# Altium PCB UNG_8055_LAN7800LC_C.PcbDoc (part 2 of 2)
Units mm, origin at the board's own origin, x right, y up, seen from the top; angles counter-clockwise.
Board outline 54.74 x 22.1 mm, 4 copper layers (Top Layer 1, Inner Layer 2, Internal Plane 3, Bottom Layer 4), stack 1.529 mm thick; 68 components, 53 nets, 222 pads, 271 vias.
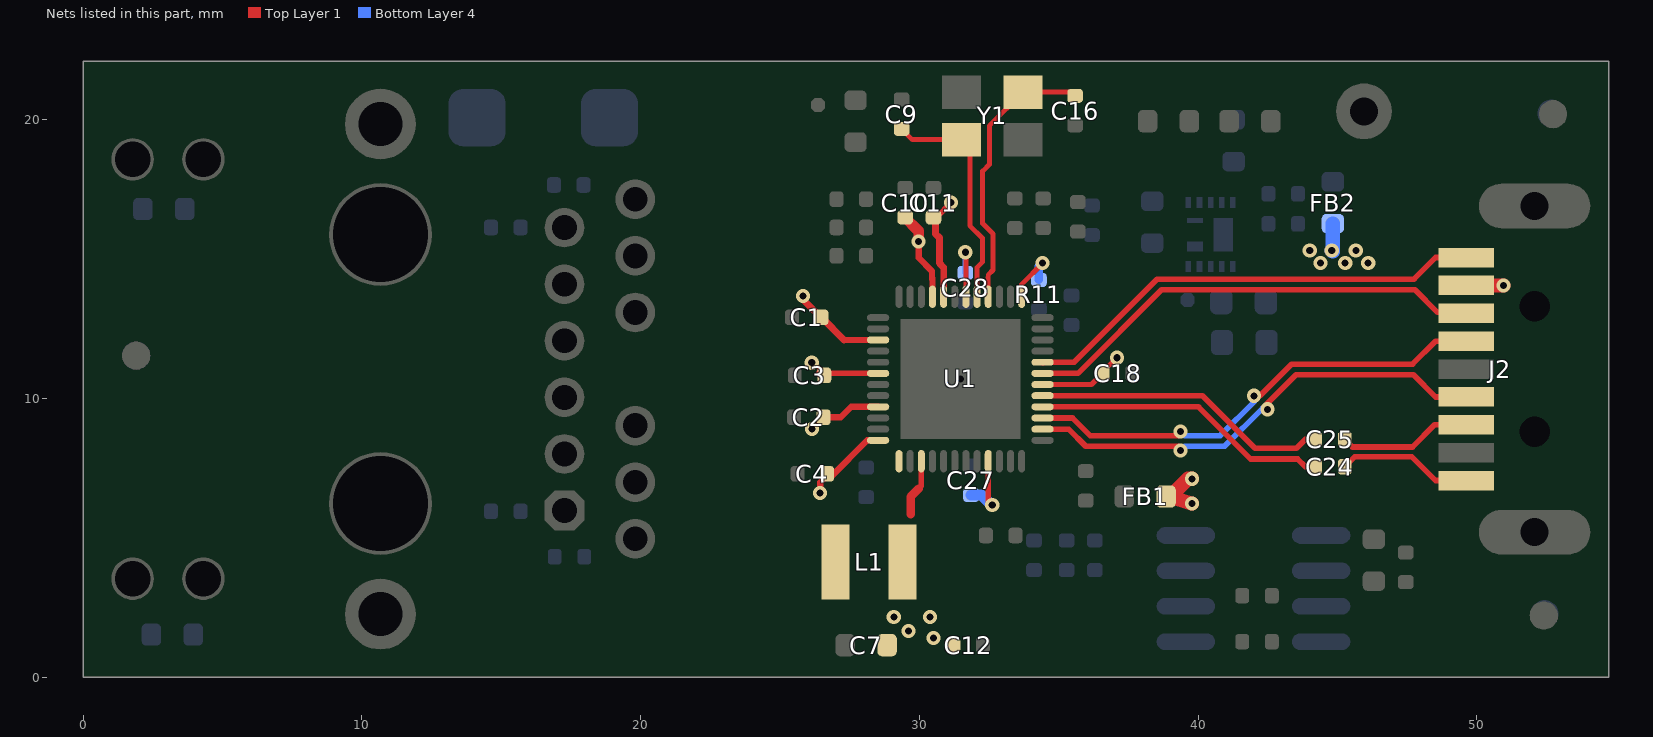
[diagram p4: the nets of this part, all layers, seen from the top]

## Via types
v1: diameter 0.508, hole 0.254, Top Layer 1 to Bottom Layer 4, tented both sides, 245 vias
v2: diameter 0.508, hole 0.254, Top Layer 1 to Bottom Layer 4, 26 vias

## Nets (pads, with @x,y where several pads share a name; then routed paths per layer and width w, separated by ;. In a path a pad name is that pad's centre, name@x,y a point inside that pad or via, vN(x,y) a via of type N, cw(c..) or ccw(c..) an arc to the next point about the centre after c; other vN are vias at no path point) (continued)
USB2D_N: J2.2 U1.27 | length 17.2
  Top Layer 1 w0.203: U1.27@34.421,9.293 35.492,9.293 36.124,8.661 39.294,8.661 39.37,8.738 v1(39.37,8.814) ; v1(42.005,10.09) 42.221,10.09 43.358,11.227 47.696,11.227 48.518,12.049 J2.2@49.62,12.049
  Bottom Layer 4 w0.203: v1(39.37,8.814) 39.522,8.661 40.792,8.661 42.037,9.906 42.037,10.058 v1(42.005,10.09)
USB2D_P: J2.3 U1.26 | length 17.2
  Top Layer 1 w0.203: U1.26@34.421,8.893 35.353,8.893 35.966,8.28 39.294,8.28 39.37,8.204 v1(39.37,8.128) ; v1(42.49,9.605) 42.49,9.821 43.516,10.846 47.722,10.846 48.518,10.049 J2.3@49.62,10.049
  Bottom Layer 4 w0.203: v1(39.37,8.128) 39.522,8.28 40.95,8.28 42.306,9.637 42.459,9.637 v1(42.49,9.605)
USB3RX_N: J2.8 U1.31 | length 17
  Top Layer 1 w0.203: U1.31@34.25,10.9 34.259,10.891 U1.31@34.421,10.891 ; U1.31@34.421,10.893 35.689,10.893 38.69,13.894 47.777,13.894 48.59,13.081 49.588,13.081 J2.8@49.62,13.049
USB3RX_P: J2.9 U1.32 | length 16.8
  Top Layer 1 w0.203: U1.32@34.417,11.272 34.421,11.272 34.434,11.272 34.438,11.276 U1.32@34.439,11.278 ; U1.32@34.421,11.293 35.55,11.293 38.532,14.275 47.744,14.275 48.518,15.049 J2.9@49.62,15.049
USB3TX1_N: C24.1 J2.5 | length 4.9
  Top Layer 1 w0.203: C24.1@45.259,7.544 45.615,7.899 47.668,7.899 48.518,7.049 J2.5@49.62,7.049
USB3TX1_P: C25.1 J2.6 | length 4.8
  Top Layer 1 w0.203: C25.1@45.259,8.531 45.536,8.255 47.688,8.255 48.482,9.049 J2.6@49.62,9.049
USB3TX_N: C24.2 U1.28 | length 10.7
  Top Layer 1 w0.203: U1.28@34.421,9.693 40.014,9.693 41.885,7.823 43.568,7.823 43.848,7.544 C24.2@44.199,7.544
USB3TX_P: C25.2 U1.29 | length 10.7
  Top Layer 1 w0.203: U1.29@34.421,10.093 40.153,10.093 42.04,8.207 43.523,8.207 43.848,8.531 C25.2@44.199,8.531
USBRBIAS: R11.2 U1.37 | length 2
  Top Layer 1 w0.178: U1.37@33.671,13.643 33.671,14.087 34.417,14.833 v1(34.417,14.859)
  Bottom Layer 4 w0.305: R11.2@34.29,14.246 v1@34.29,14.732
VBUS: FB2.1 J2.1 | length 2.4
  Top Layer 1 w0.254: v1(50.95,14.049) v1@50.955,14.049
  Top Layer 1 w0.508: J2.1@49.62,14.049 v1(50.95,14.049)
  Bottom Layer 4 w0.508: v1(44.793,15.303) 44.831,15.265 FB2.1@44.831,16.268
  other v1: 44.386,14.859 45.275,14.859 46.101,14.859 44.005,15.303 45.656,15.303
VDD12: C7.2 C11.2 C12.2 C18.2 C27.2 C28.2 FB1.2 L1.2 U1.15 U1.21 U1.30 U1.42 U1.44 | length 15.5
  Top Layer 1 w0.178: U1.42@31.671,13.643 v1@31.671,15.218 ; U1.30@34.421,10.493 36.173,10.493 C18.2@36.576,10.897 ; C18.2@36.579,10.897 36.579,10.951 v1@37.059,11.43
  Top Layer 1 w0.203: 29.972,6.756 30.071,6.855 U1.15@30.071,7.743 ; C11.2@30.505,16.488 30.61,16.488 v1(31.14,17.018) ; U1.21@32.471,7.743 32.471,6.239 v1@32.588,6.121
  Top Layer 1 w0.229: U1.44@30.871,13.643 30.871,14.697
  Top Layer 1 w0.254: C11.2@30.505,16.383 30.582,16.307 30.582,15.898 30.721,15.759 30.721,14.847 30.871,14.697 ; v1(31.648,15.24) v1@31.671,15.218
  Top Layer 1 w0.305: 29.693,5.842 29.693,6.477 29.972,6.756
  Top Layer 1 w0.508: v1(39.776,6.223) 39,6.477 39.635,7.112 v1(39.776,7.112)
  Bottom Layer 4 w0.203: C28.2@31.648,14.5 v1@31.648,15.113
  Bottom Layer 4 w0.381: C27.2@31.852,6.531 32.229,6.531 v1@32.588,6.172
  other v1: 30.505,1.397 29.616,1.651 29.083,2.159 30.378,2.159 32.614,6.172 37.084,11.455
VDD12_SW_OUT: L1.1 U1.13
VDD25: C1.2 C2.2 C3.2 C4.2 C10.2 U1.3 U1.6 U1.9 U1.12 U1.45 | length 16.1
  Top Layer 1 w0.152: v1@25.991,8.903 v1(26.153,8.903) ; v1@26.067,11.125 v1@26.141,11.199 ; v1(26.141,11.277) v1@26.141,11.199 ; C3.2@26.437,10.943 26.459,10.922 26.48,10.943 26.51,10.973 26.212,11.27 v1@26.141,11.199
  Top Layer 1 w0.178: v1(26.153,8.903) 26.06,8.81 26.037,8.786 ccw(c26.037,8.899) 26.116,8.819 C2.2@26.594,9.296
  Top Layer 1 w0.203: C3.2@26.667,10.893 U1.6@28.521,10.893 ; 27.302,12.093 U1.3@28.521,12.093
  Top Layer 1 w0.229: v1(26.441,6.604) 26.441,6.985 26.692,7.236 C4.2@26.692,7.29 ; C3.2@26.518,10.744 C3.2@26.667,10.893 ; C2.2@26.565,9.322 27.179,9.322 27.551,9.693 U1.9@28.521,9.693 ; C4.2@26.692,7.188 26.829,7.188 28.135,8.493 U1.12@28.521,8.493 ; v1(29.972,15.621) 29.972,15.039 30.455,14.556 30.455,14.275 ; U1.45@30.471,13.643 30.471,14.31
  Top Layer 1 w0.254: v1(25.832,13.665) 25.832,13.538 C1.2@26.454,12.916 ; C3.2@26.437,10.943 26.48,10.943 C3.2@26.67,10.943 ; C1.2@26.518,12.878 27.302,12.093
  Top Layer 1 w0.381: C10.2@29.464,16.51 29.972,16.002 v1(29.972,15.621)
XI: C16.2 U1.40 Y1.3 | length 10.1
  Top Layer 1 w0.178: 32.461,14.326 32.471,14.335 ; U1.40@32.471,13.643 32.471,14.335 ; C16.2@35.585,20.828 35.433,20.98 Y1.3@33.718,20.98 32.512,19.774 32.512,18.39 32.271,18.148 32.271,16.269 32.639,15.9 32.639,14.6 32.471,14.431 32.471,14.335
XO: C9.2 U1.41 Y1.1 | length 8.3
  Top Layer 1 w0.178: C9.2@29.362,19.663 29.747,19.279 Y1.1@31.509,19.279 ; Y1.1@31.557,19.238 31.813,18.981 31.813,16.192 32.258,15.748 32.258,14.884 32.071,14.697 U1.41@32.071,13.643
pads on no net: FID1.1 FID2.1 FID3.1 FID4.1 FID5.1 FID6.1 J2.MH U3.7

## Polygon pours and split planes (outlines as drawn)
GND on Top Layer 1 "Top Layer-No Net" (solid, pour order 68): 52.299,13.284 50.444,13.284 50.267,13.462 50.241,13.487 49.454,13.487 46.457,13.487 46.406,13.487 46.152,13.741 46.126,13.767 46.126,13.919 46.126,14.3 46.279,14.453 46.304,14.478 46.457,14.478 50.927,14.478 51.46,13.945 51.689,13.716 52.299,13.716
NetC17_2 on Top Layer 1 "Top Layer-No Net" (solid, pour order 50): 37.49,6.096 37.49,6.858 37.49,7.112 37.363,7.239 36.982,7.239 36.601,7.239 36.093,7.747 35.331,8.509 34.95,8.509 34.315,8.509 34.188,8.382 34.188,8.255 34.569,7.874 34.696,7.874 34.823,7.874 35.458,7.239 35.585,7.112 36.093,7.112 36.22,7.112 36.474,6.858 36.474,6.477 36.474,6.096 36.601,5.969 37.109,5.969 37.363,5.969 37.49,6.096
VDD12 on Top Layer 1 "Top Layer-No Net" (solid, pour order 8): 28.892,2.603 28.702,2.413 28.702,1.27 28.702,0.889 28.829,0.762 29.21,0.762 31.369,0.762 31.369,1.016 31.369,1.651 31.242,1.778 30.226,2.794 30.226,3.683 30.226,5.969 29.972,6.223 29.845,6.35 29.591,6.35 29.337,6.096 28.892,5.651
VDD12_SW_OUT on Top Layer 1 "Top Layer-No Net" (solid, pour order 18): 26.314,2.718 27.419,2.718 27.876,3.175 27.876,6.032 28.219,6.375 28.854,7.01 29.362,7.518 29.362,8.128 28.981,8.128 28.473,7.62 28.016,7.62 27.457,7.061 25.844,5.448 25.844,3.188
3V3_BOARD on Top Layer 1 "Top Layer-No Net" (solid, pour order 28): 33.426,13.462 33.426,14.224 33.426,14.351 34.442,15.367 34.696,15.621 34.696,15.875 34.696,16.256 34.315,16.256 33.172,16.256 33.045,16.129 33.045,16.002 33.045,14.605 32.791,14.351 32.791,13.335 33.426,13.335
3V3_BOARD on Top Layer 1 "Top Layer-No Net" (solid, pour order 32): 34.112,12.776 34.519,12.776 34.9,12.776 35.712,13.589 35.712,14.224 35.712,14.478 35.585,14.605 35.458,14.732 35.331,14.732 35.204,14.732 34.823,14.351 34.823,13.589 34.823,13.335 34.569,13.081 34.188,13.081 34.061,12.954 34.061,12.827
GND on Top Layer 1 "Top Layer-No Net" (solid, pour order 64): 37.668,14.224 38.303,14.224 38.43,14.351 38.43,14.478 38.43,14.732 38.43,15.748 38.811,16.129 38.938,16.256 39.827,16.256 40.589,16.256 40.716,16.383 40.716,16.764 40.716,19.05 40.589,19.177 40.081,19.177 39.192,19.177 39.065,19.304 39.065,19.431 39.065,20.066 39.065,20.32 38.938,20.447 37.795,20.447 37.668,20.447 37.541,20.32 37.541,19.685 37.541,19.304 37.668,19.177 37.922,19.177 38.557,19.177 38.938,18.796 39.065,18.669 39.065,18.161 39.065,17.78 39.192,17.653 39.446,17.653 40.208,17.653 40.335,17.526 40.335,17.399 40.335,16.637 40.208,16.51 39.954,16.51 39.573,16.51 39.065,16.51 37.287,16.51 37.16,16.383 37.16,16.129 37.16,14.351 37.287,14.224
GND on Top Layer 1 "Top Layer-No Net" (solid, pour order 66): 14.034,0.635 54.229,0.635 54.229,21.59 43.18,21.59 14.034,21.59
RJ45_CHASSIS on Top Layer 1 "Top Layer-No Net" (solid, pour order 76): 0.508,0.635 13.843,0.635 13.843,21.59 0.508,21.59
VBUS on Bottom Layer 4 "Top Layer-No Net" (solid, pour order 52): 43.434,15.596 43.713,15.875 44.094,16.256 46.126,16.256 46.507,15.875 46.507,15.113 46.507,14.732 46.38,14.605 46.253,14.478 44.602,14.478 43.434,14.478
5V_BOARD on Bottom Layer 4 "Top Layer-No Net" (solid, pour order 60): 40.894,17.59 41.148,17.335 42.189,17.335 45.352,17.335 45.415,17.399 45.491,17.475 45.491,17.932 45.491,18.593 45.415,18.669 45.314,18.771 44.298,18.771 41.059,18.771 40.894,18.605
3V3_BOARD on Bottom Layer 4 "Top Layer-No Net" (solid, pour order 56): 37.389,16.764 38.659,16.764 38.938,16.764 39.065,16.764 39.446,16.764 39.446,17.399 38.938,17.399 38.811,17.526 38.811,17.78 38.811,18.542 38.811,18.669 38.684,18.796 37.414,18.796 37.16,18.796 37.033,18.669 37.033,18.288 37.033,16.891 37.16,16.764
VDD25 on Bottom Layer 4 "Top Layer-No Net" (solid, pour order 22): 26.949,6.477 26.949,13.589 27.711,14.351 30.251,14.351 30.366,14.465 30.366,15.113 30.378,15.24 30.378,15.494 30.378,15.748 30.251,15.875 29.997,15.875 29.108,15.875 27.33,15.875 26.314,15.875 26.187,15.875 26.06,15.875 25.806,15.875 26.441,15.621 25.425,15.621 25.425,14.351 25.425,13.97 25.425,13.462 25.425,6.35 25.679,6.096 26.314,6.096 26.695,6.096 26.822,6.223 26.949,6.35
GND on Bottom Layer 4 "Top Layer-No Net" (solid, pour order 26): 27.711,7.112 34.696,7.112 35.966,7.112 36.347,7.493 36.347,10.033 36.347,12.446 36.22,12.573 35.966,12.827 35.458,12.827 34.95,12.827 34.823,12.827 34.696,12.954 34.696,13.335 34.696,13.589 32.41,13.589 27.584,13.589 27.33,13.335 27.33,12.573 27.33,7.366 27.584,7.112
GND on Bottom Layer 4 "Top Layer-No Net" (solid, pour order 70): 14.034,0.635 54.229,0.635 54.229,21.59 43.18,21.59 14.034,21.59
RJ45_CHASSIS on Bottom Layer 4 "Top Layer-No Net" (solid, pour order 78): 0.508,0.635 13.843,0.635 13.843,21.59 0.508,21.59
GND on Inner Layer 2 (split plane): 54.354,0.383 14.327,0.383 14.327,21.715 54.354,21.715
RJ45_CHASSIS on Inner Layer 2 (split plane): 13.562,0.383 0.383,0.383 0.383,21.715 13.562,21.715
VBUS on Internal Plane 3 (split plane): 51.242,14.678 51.242,13.833 50.873,13.464 44.123,13.464 43.78,13.808 43.5,14.087 43.5,15.44 44.186,16.127 49.794,16.127
3V3_BOARD on Internal Plane 3 (split plane): 46.924,20.711 46.924,20.002 46.924,19.739 46.2,19.015 45.793,18.608 45.085,18.608 45.035,18.598 44.993,18.57 41.945,15.522 41.917,15.48 41.908,15.43 41.908,14.722 41.793,14.607 36.703,14.607 36.653,14.598 36.611,14.57 36.078,14.036 36.05,13.994 36.04,13.945 36.04,13.591 35.296,13.591 32.21,16.678 32.21,17.907 32.2,17.957 32.172,17.999 31.664,18.507 31.622,18.535 31.572,18.544 30.937,18.544 30.888,18.535 30.846,18.507 30.452,18.113 30.424,18.071 30.414,18.021 30.414,15.824 30.424,15.775 30.452,15.733 31.671,14.513 31.713,14.485 31.763,14.476 32.014,14.476 32.039,14.45 34.11,12.38 34.11,8.309 33.17,7.368 32.893,7.368 32.843,7.359 32.801,7.331 32.547,7.077 31.862,6.391 31.834,6.349 31.824,6.299 31.824,5.207 31.834,5.157 31.862,5.115 32.116,4.861 32.158,4.833 32.207,4.824 35.1,4.824 35.888,4.036 35.888,2.975 35.329,2.415 31.598,2.415 31.585,2.413 31.572,2.415 31.245,2.415 30.902,2.759 30.86,2.787 30.81,2.796 28.514,2.796 28.514,2.857 28.514,6.614 28.756,6.856 30.289,6.856 30.339,6.865 30.381,6.893 31.905,8.417 31.933,8.459 31.943,8.509 31.943,12.255 31.933,12.305 31.905,12.347 29.022,15.23 29.022,17.335 29.012,17.385 28.984,17.427 28.413,17.999 28.371,18.027 28.321,18.036 16.818,18.036 16.512,18.342 16.512,19.06 16.792,19.339 16.881,19.429 42.418,19.429 42.468,19.438 42.51,19.466 44.123,21.08 46.555,21.08
VDD12 on Internal Plane 3 (split plane): 31.951,17.853 31.951,16.624 31.961,16.575 31.989,16.533 32.674,15.847 33.055,15.466 35.151,13.37 35.193,13.342 35.242,13.333 36.116,13.333 37.539,11.91 37.539,11.204 36.789,10.455 36.761,10.413 36.751,10.363 36.751,10.033 36.751,8.509 36.761,8.459 36.789,8.417 37.234,7.973 37.276,7.945 37.325,7.935 38.808,7.935 39.278,7.465 39.32,7.437 39.37,7.427 39.837,7.427 40.206,7.058 40.206,6.921 40.206,5.105 40.206,4.191 40.206,2.642 40.206,0.383 28.514,0.383 28.514,1.918 28.514,2.538 30.757,2.538 31.1,2.194 31.142,2.166 31.191,2.157 31.572,2.157 31.585,2.159 31.598,2.157 35.382,2.157 35.432,2.166 35.474,2.194 36.109,2.829 36.137,2.871 36.147,2.921 36.147,4.089 36.137,4.139 36.109,4.181 35.245,5.045 35.203,5.073 35.154,5.082 32.261,5.082 32.083,5.261 32.083,6.246 32.731,6.893 32.947,7.11 33.223,7.11 33.273,7.119 33.315,7.147 34.331,8.163 34.359,8.205 34.369,8.255 34.369,12.433 34.359,12.483 34.331,12.525 32.223,14.633 32.159,14.697 32.117,14.725 32.067,14.734 31.816,14.734 30.673,15.878 30.673,17.968 30.991,18.286 31.519,18.286
RJ45_CHASSIS on Internal Plane 3 (split plane): 13.587,0.383 0.383,0.383 0.383,21.715 13.587,21.715
GND on Internal Plane 3 (split plane): 54.354,0.383 40.465,0.383 40.465,2.642 40.465,5.105 40.465,7.112 40.455,7.162 40.427,7.204 39.982,7.648 39.94,7.676 39.891,7.686 39.424,7.686 38.954,8.156 38.912,8.184 38.862,8.194 37.379,8.194 37.01,8.563 37.01,10.31 37.76,11.059 37.788,11.101 37.798,11.151 37.798,11.963 37.788,12.013 37.76,12.055 36.299,13.516 36.299,13.891 36.757,14.349 41.846,14.349 41.896,14.358 41.938,14.386 42.129,14.577 42.157,14.619 42.166,14.668 42.166,15.377 45.139,18.349 45.847,18.349 45.897,18.359 45.939,18.387 46.383,18.831 47.145,19.593 47.173,19.635 47.183,19.685 47.183,20.764 47.173,20.814 47.145,20.856 46.701,21.301 46.659,21.329 46.609,21.338 44.069,21.338 44.019,21.329 43.977,21.301 42.364,19.687 16.827,19.687 16.778,19.678 16.736,19.65 16.609,19.523 16.291,19.205 16.263,19.163 16.254,19.113 16.254,18.288 16.263,18.238 16.291,18.196 16.672,17.815 16.714,17.787 16.764,17.778 28.267,17.778 28.763,17.282 28.763,15.176 28.773,15.127 28.801,15.085 31.684,12.202 31.684,8.563 30.236,7.114 28.702,7.114 28.652,7.105 28.61,7.077 28.293,6.759 28.265,6.717 28.255,6.667 28.255,2.857 28.255,2.667 28.255,1.918 28.255,0.383 14.353,0.383 14.353,21.715 54.354,21.715

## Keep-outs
Keep-Out Layer:
  text ".Layer_Name" at 239.425,-136.66 h0.51

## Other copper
Top Layer 1:
  pour cut-out: 29.019,13.208 33.972,13.208 33.972,8.191 29.019,8.191
  text ".Layer_Name" at -4.293,-12.065 h1.52
  text ".Layer_Name" at 250.114,-136.296 h2.54
  text ".ProjectRevisionART" at 272.499,-136.503 h2.54
Bottom Layer 4:
  region net NetTP2_1: 39.56,15.113 39.624,15.176 39.624,15.621 40.132,15.621 40.132,14.541 39.56,14.541
  region net 3V3_BOARD: 39.56,17.081 40.132,17.081 40.132,16.701 40.195,16.637 40.195,16.256 39.56,16.256
  pour cut-out: 12.217,18.517 12.344,18.39 15.545,18.39 15.926,18.771 15.926,21.311 15.697,21.539 12.421,21.539 12.217,21.336
  text "PCB-UNG8055-C0" at 6.794,14.922 h1.4 r90
  text ".Layer_Name" at -4.166,-11.938 h1.52
  text ".Layer_Name" at 250.063,-136.398 h2.54
  text ".ProjectRevisionART" at 272.517,-136.5 h2.54
Inner Layer 2 (plane layer: these items are gaps in the copper):
  lines w0.762: 13.945,0 13.945,22.034
  text ".Layer_Name" at -3.607,-11.836 h2.79
  text ".Layer_Name" at 249.936,-136.398 h2.79
  text ".ProjectRevisionART" at 272.499,-136.503 h2.54
Internal Plane 3 (plane layer: these items are gaps in the copper):
  lines w0.254: 28.397,0.127 28.384,0.14 28.384,1.918 28.384,2.857 28.384,2.667 ; 31.572,2.286 31.191,2.286 30.81,2.667 28.384,2.667 ; 31.598,2.286 35.382,2.286 36.017,2.921 36.017,4.089 35.154,4.953 34.011,4.953 ; 32.766,15.938 33.147,15.557 ; 33.083,7.239 32.893,7.239 ; 34.239,4.953 32.207,4.953 31.953,5.207 31.953,6.299 32.639,6.985 32.893,7.239 ; 36.881,10.033 36.881,10.363 ; 40.335,0 40.335,2.642 40.335,5.105 ; 40.335,4.191 40.335,7.112 ; 40.335,6.921 40.335,7.112 ; 46.291,18.923 45.847,18.479 ; 47.053,20.002 47.053,19.685 ; 28.384,2.667 28.384,6.667 28.702,6.985 29.591,6.985 30.289,6.985 31.813,8.509 31.813,12.255 28.892,15.176 28.892,17.335 28.321,17.907 28.003,17.907 16.764,17.907 16.383,18.288 16.383,19.113 16.7,19.431 16.827,19.558 42.418,19.558 44.069,21.209 46.609,21.209 47.053,20.764 47.053,19.685 ; 32.893,7.239 33.223,7.239 34.239,8.255 34.239,12.433 32.131,14.541 32.067,14.605 31.763,14.605 30.543,15.824 30.543,18.021 30.937,18.415 31.572,18.415 32.08,17.907 32.08,16.624 35.242,13.462 35.814,13.462 ; 35.814,13.462 36.17,13.462 ; 35.814,13.462 36.17,13.462 ; 36.17,13.462 36.17,13.945 36.703,14.478 41.846,14.478 42.037,14.668 42.037,15.43 45.085,18.479 45.847,18.479 ; 36.17,13.462 37.668,11.963 37.668,11.151 36.881,10.363 ; 36.881,10.363 36.881,8.509 37.325,8.064 38.862,8.064 39.37,7.556 39.891,7.556 40.335,7.112 ; 45.847,18.479 47.053,19.685 ; 43.37,14.034 43.37,15.494 44.132,16.256 49.847,16.256 51.371,14.732 51.371,13.779 50.927,13.335 44.069,13.335 43.688,13.716 43.37,14.034
  lines w0.762: 13.97,0 13.97,22.098
  text ".Layer_Name" at -3.962,-12.217 h2.79
  text ".ProjectRevisionART" at 272.517,-136.5 h2.54
  text ".Layer_Name" at 250.317,-136.652 h2.79

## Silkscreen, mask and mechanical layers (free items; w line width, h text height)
Top Overlay:
  lines w0.254: 0.508,20.149 4.318,20.149 8.588,20.149
  text "PME" at 23.622,19.748 h1.37
  text "\"3V3\"" at 40.576,17.97 h1.52
  text "3V3" at 45.021,17.843 h1.52
  text "*h" at 35.115,12.383 h2.79
  text "LAN7800" at 35.306,8.826 h1.91
  text "USB3.1-A /  to GbE" at 33.274,0.635 h2.03
  text ".ProjectRevisionART" at 272.499,-136.503 h2.54
  text ".Layer_Name" at 249.809,-136.576 h2.54
Bottom Overlay:
  rectangle: 12.268,0.318 27.686,3.429
  text "" at 53.848,12.573 h5.08 r90
  text "" at 7.874,9.335 h8.89
  text "C" at 7.683,9.017 h3.81
  text "e" at 7.938,5.08 h3.81
  text "S/N:" at 26.543,3.683 h2.29
  text ".ProjectRevisionART" at 272.499,-136.503 h2.54
  text ".Layer_Name" at 250.063,-136.576 h2.54
Top Paste:
  text ".Layer_Name" at 249.987,-136.347 h2.54
  text ".ProjectRevisionART" at 272.499,-136.503 h2.54
Bottom Paste:
  text ".ProjectRevisionART" at 272.499,-136.503 h2.54
  text ".Layer_Name" at 249.885,-136.55 h2.54
Top Solder:
  region: 47.955,5.207 47.955,4.318 50.241,4.318 50.368,4.445 50.368,5.08 50.241,5.207
  region: 48.336,16.891 47.828,16.891 47.828,16.383 47.828,16.002 48.336,16.002 50.622,16.002 50.749,16.129 50.749,16.764 50.622,16.891
  text ".Layer_Name" at 249.987,-136.347 h2.54
  text ".ProjectRevisionART" at 272.499,-136.503 h2.54
Bottom Solder:
  region: 47.955,5.207 47.955,4.318 50.241,4.318 50.368,4.445 50.368,5.08 50.241,5.207
  region: 48.336,16.891 47.828,16.891 47.828,16.383 47.828,16.002 48.336,16.002 50.622,16.002 50.749,16.129 50.749,16.764 50.622,16.891
  text ".ProjectRevisionART" at 272.499,-136.503 h2.54
  text ".Layer_Name" at 251.257,-136.652 h2.54
NOTES (M1):
  text ".Layer_Name" at 279.4,-119.228 h0.51
BOARD (M2):
  lines w0.127: 0,0 0,22.098 53.594,22.098 54.737,22.098 54.737,0 0,0
  text ".ProjectRevisionART" at 284.658,-119.38 h0.51
REF POINTS (M3):
  text ".Layer_Name" at 239.425,-136.66 h0.51
FAB (M4):
  text ".Layer_Name" at 252.222,-136.068 h1.52
Case (M5):
  text ".Layer_Name" at 239.425,-136.66 h0.51
Cover (M6):
  text ".Layer_Name" at 239.425,-136.66 h0.51
Terminal Block (M7):
  text ".Layer_Name" at 239.425,-136.66 h0.51
Milling (M8):
  text ".Layer_Name" at 239.425,-136.66 h0.51
V-Cut (M9):
  text ".Layer_Name" at 239.425,-136.66 h0.51
Assy BOT (M10):
  text "DOCUMENT NUMBER:" at -43.025,-128.91 h0.51
  text "-D" at -57.025,-131.91 h0.51
  text ".ProjectBoardNumber" at -48.775,-131.91 h0.51
  text "02-" at -43.275,-131.91 h0.51
  text ".ProjectRevisionASSY" at -59.953,-136.482 h0.51
  text ".Layer_Name" at -25.075,-136.66 h0.51
Assy TOP (M11):
  text "ASSEMBLY NOTES:" at -2.635,-23.275 h2.54
  text "1. WORKMANSHIP TO BE COMPLIANT WITH IPC-A-610, CLASS 2." at -3.163,-25.851 h2.54
  text "2. ALL UNUSED THROUGH HOLE COMPONENT LOCATIONS SHALL BE FREE OF SOLDER." at -3.163,-28.851 h2.54
  text "3. ALL COMPONENTS SHALL BE MOUNTED FLUSH TO THE BOARD, EXCEPT AS NOTED." at -3.163,-31.851 h2.54
  text "4. FINISHED BOARD SHALL BE FREE OF ALL RESIDUES." at -3.163,-34.851 h2.54
  text "5. THIS ASSEMBLY CONTAINS ELECTROSTATIC DISCHARGE (ESD) SENSITIVE DEVICES; STATIC-FREE HANDLING IS REQUIRED." at -3.163,-37.851 h2.54
  text "6. PRODUCT WILL BE ASSEMBLED USING RoHS COMPLIANT MANUFACTURING PROCESS AND COMPONENTS." at -3.087,-41.052 h2.54
  text "7. PLACE S/N LABEL INSIDE S/N BOX ON BOTTOM SIDE" at -3.061,-43.891 h2.54
  text "DOCUMENT NUMBER:" at 257.675,-128.91 h1.91
  text ".ProjectBoardNumber" at 261.874,-131.877 h1.91
  text "02-" at 257.925,-131.91 h1.91
  text "-D" at 271.675,-131.91 h0.51
  text ".Layer_Name" at 250.698,-136.195 h2.54
3D BOT (M12):
  text ".Layer_Name" at 239.425,-136.66 h0.51
3D TOP (M13):
  text ".Layer_Name" at 239.425,-136.66 h0.51
Guard BOT (M14):
  text ".ProjectRevisionART" at 272.364,-136.525 h2.54
  text ".Layer_Name" at 239.425,-136.66 h0.51
Guard TOP (M15):
  lines w0.025: 48.336,15.215 49.276,15.215 51.079,15.215 51.079,14.861 ccw(c51.513,14.861) 51.206,14.554 ccw(c51.452,14.799) 51.452,14.453 51.518,14.453 ccw(c51.518,14.804) 51.766,14.555 ccw(c51.463,14.859) 51.892,14.859 54.432,14.859 54.432,6.502 49.962,6.502 49.936,6.477 49.936,6.071
  text ".ProjectRevisionART" at 272.364,-136.525 h2.54
  text ".Layer_Name" at 239.425,-136.66 h0.51
TITLE (M16):
  lines w0.1: 256.925,-111.91 256.925,-114.91 292.745,-114.91 ; 281.465,-136.545 281.465,-135.275 ; 281.465,-135.91 291.625,-135.91 ; 281.625,-134.71 281.625,-133.71 ; 281.625,-134.21 291.625,-134.21 ; 284.005,-136.545 284.005,-135.275 ; 286.545,-136.545 286.545,-135.275 ; 286.625,-134.51 286.625,-133.91 ; 289.085,-136.545 289.085,-135.275 ; 291.625,-136.545 291.625,-135.275 ; 291.625,-134.71 291.625,-133.71
  lines w0.127: -83.175,-82.085 -78.095,-82.085 ; -83.175,-21.76 -78.095,-21.76 ; -83.175,38.565 -78.095,38.565 ; -19.675,-142.41 -19.675,-137.33 ; -19.675,93.81 -19.675,98.89 ; 43.825,-142.41 43.825,-137.33 ; 43.825,93.81 43.825,98.89 ; 107.325,-142.41 107.325,-137.33 ; 107.325,93.81 107.325,98.89 ; 142.885,-137.33 178.445,-137.33 ; 170.825,-142.41 170.825,-137.33 ; 170.825,93.81 170.825,98.89 ; 176.925,-137.33 176.925,-111.91 292.745,-111.91 ; 210.925,-137.33 210.925,-111.91 ; 210.925,-132.91 292.745,-132.91 ; 210.925,-126.91 292.745,-126.91 ; 210.925,-120.91 292.745,-120.91 ; 234.325,-142.41 234.325,-137.33 ; 234.325,93.81 234.325,98.89 ; 238.925,-137.33 238.925,-120.91 ; 256.925,-132.91 256.925,-126.91 ; 269.925,-137.33 269.925,-132.91 ; 277.425,-137.33 277.425,-126.91 ; 292.745,-106.85 292.745,-137.33 ; 292.745,-21.76 297.825,-21.76 ; 292.747,-82.05 297.827,-82.05 ; 292.747,38.6 297.827,38.6 ; 292.745,-137.33 -78.095,-137.33 -78.095,93.81 292.745,93.81 292.745,-137.33 ; -83.175,-142.41 297.825,-142.41 297.825,98.89 -83.175,98.89 -83.175,-142.41
  lines w0.254: 170.925,93.59 170.925,89.09 ; 181.925,84.59 181.925,89.09 181.925,93.59 ; 194.425,84.59 194.425,89.09 194.425,93.59 ; 272.925,84.59 272.925,89.09 272.925,93.59 ; 292.425,84.59 170.925,84.59 170.925,89.09 ; 292.425,89.09 170.925,89.09
  text "1" at -51.899,95.588 h0.51
  text "2" at 11.491,95.588 h0.51
  text "3" at 74.72,95.588 h0.51
  text "4" at 138.389,95.588 h0.51
  text "5" at 201.864,95.588 h0.51
  text "6" at 265.491,95.588 h0.51
  text "REV" at 173.425,90.59 h0.51
  text "ECO" at 183.425,90.59 h0.51
  text "Comments" at 229.925,90.09 h0.51
  text "Date" at 277.925,90.09 h0.51
  text "A" at -81.27,66.556 h0.51
  text "A" at 294.65,66.556 h0.51
  text "B" at -81.27,6.104 h0.51
  text "B" at 294.65,6.104 h0.51
  text "C" at -81.27,-54.221 h0.51
  text "C" at 294.703,-54.44 h0.51
  text "PROJECT PART NUMBER:" at 257.925,-113.91 h0.51
  text ".ProjectpartNumber" at 268.605,-114.351 h2.54
  text "D" at -81.27,-114.419 h0.51
  text "D" at 294.65,-114.419 h0.51
  text "TITLE:" at 212.776,-115.316 h2.54
  text ".ProjectTitle" at 223.342,-118.135 h3.05
  text "PCB DESIGNER:" at 211.925,-122.91 h0.51
  text "GERBER FILE:" at 239.925,-122.91 h0.51
  text "M" at 182.956,-124.917 h11.43
  text ".ProjectDrawnBy" at 217.678,-125.222 h3.05
  text ".Plot_File_Name" at 239.925,-125.91 h0.51
  text "ENGINEER:" at 211.925,-128.91 h1.52
  text "BOARD NUMBER:" at 239.925,-128.91 h0.51
  text "DATE:" at 278.625,-128.91 h0.51
  text "Microchip Technology Inc." at 183.159,-129.337 h2.54
  text ".PRINT_DATE" at 278.625,-131.91 h3.05
  text "2355 W. Chandler Blvd." at 183.083,-131.953 h2.54
  text ".ProjectEngineer" at 217.551,-132.08 h3.05
  text "04-" at 239.522,-132.258 h2.54
  text "UNG-8055" at 243.967,-132.258 h3.05
  text "Chandler, AZ  85224" at 182.956,-134.366 h2.54
  text "LAYER NAME:" at 239.925,-134.41 h1.02
  text "10mm" at 277.925,-134.51 h0.51
  text "PCB FILE NAME:" at 211.925,-134.66 h0.51
  text "REV:" at 270.675,-134.66 h0.51
  text "400mil" at 277.825,-136.21 h0.51
  text ".PCB_FILE_NAME_NO_PATH" at 211.925,-136.66 h2.03
  text "1" at -51.899,-140.632 h0.51
  text "2" at 11.491,-140.632 h0.51
  text "3" at 74.72,-140.632 h0.51
  text "4" at 138.389,-140.632 h0.51
  text "5" at 201.864,-140.632 h0.51
  text "6" at 265.491,-140.632 h0.51
Drill Drawing:
  drawing of 374 lines, arcs and shapes, not listed
  text "NOTE UNLESS OTHERWISE SPECIFIED:" at 134.518,69.494 h3.81
  text "1.  Base Material 370HR or NP-175, Rohs compliant and compatible." at 134.518,65.049 h3.81
  text "2.  PCB thickness: 0.062, +/- 0.007\" finished." at 134.518,60.604 h3.81
  text "3.  PCB Construction: 4 layers." at 134.421,54.906 h3.81
  text "This construction shall be as detailed per Layer Stackup Table." at 138.328,51.079 h3.81
  text "4. Conductive Pattern finish: IPC ENIG (Au over Ni)." at 134.611,46.905 h3.81
  text "5. Soldermask: Soldermask over bare copper, \"Blue\", both sides." at 134.611,43.095 h3.81
  text "Soldermask shall be in accordance with IPC-SM-840 Class T." at 138.421,39.285 h3.81
  text "There shall be no soldermask on any land." at 138.421,35.475 h3.81
  text "6. Silkscreen: DO NOT clear silkscreen from tented vias." at 134.621,30.552 h3.81
  text "White, permanent, non-conductive ink: Applied to both sides." at 138.421,26.585 h3.81
  text "There shall be no ink on any exposed land." at 138.421,22.775 h3.81
  text "7. Board fabrication acceptance shall meet IPC-6012B Class 2 workmanship requirements, except as noted." at 134.611,17.695 h3.81
  text "8. Minimum copper plate in all holes to be 0.001 inches." at 134.611,12.615 h3.81
  text "9. Copper thieving may be added by the PCB fabricator on inner and outer layers" at 134.738,8.107 h3.81
  text "to assist the plating process ONLY IF:" at 137.897,4.369 h3.81
  text "A. All thieving pads are kept at least 55 mils from other features." at 139.183,-0.11 h3.81
  text "B. The thieving pattern is made up of individual and separate pads." at 139.183,-3.92 h3.81
  text "11" at 19.138,-7.117 h3.81
  text "(No hatching or grid lines.)" at 138.421,-8.111 h3.81
  text "10. PCB must be tested per IPC-9252 Class 2. Any diviation from this" at 134.582,-12.802 h3.81
  text "requirement must have written authorization from Microchip Technology Inc." at 139.183,-16.62 h3.81
  text "11.  Vendor ID, UL rating, date code and/or lot number must appear on this board in" at 134.675,-21.637 h3.81
  text "copper located as shown on bottom side." at 139.916,-25.057 h3.81
  text "12. Finished drill hole size tolerances unless otherwise specified;" at 134.675,-30.717 h3.81
  text "Under 0.021 inches: +0.003/ -0.006" at 139.755,-34.527 h3.81
  text "0.021 to 0.090 inches: +/- 0.003" at 139.755,-38.337 h3.81
  text "Over 0.090 inches: +/- 0.006" at 139.755,-42.147 h3.81
  text "Symbol" at -60.389,-43.842 h1.83
  text "Count" at -47.539,-43.842 h1.83
  text "Hole Size" at -32.303,-43.842 h1.83
  text "Plated" at -3.102,-43.842 h1.83
  text "Hole Type" at 9.747,-43.842 h1.83
  text "Via/Pad" at 28.386,-43.842 h1.83
  text "13. Traces shall finish at the artwork width, +/- 1 mil." at 134.709,-47.282 h3.81
  text "1" at -47.539,-47.652 h1.52
  text "39.37mil (1.000mm)" at -32.303,-47.652 h1.52
  text "PTH" at -3.102,-47.652 h1.52
  text "Round" at 9.747,-47.652 h1.52
  text "Pad" at 28.386,-47.652 h1.52
  text "2" at -47.539,-51.462 h1.52
  text "39.37mil (1.000mm)" at -32.303,-51.462 h1.52
  text "PTH" at -3.102,-51.462 h1.52
  text "Slot" at 9.747,-51.462 h1.52
  text "Pad" at 28.386,-51.462 h1.52
  text "14. Miniumum Trace and Space = 6 mil / 5 mil (ref.)" at 134.709,-51.727 h3.81
  text "2" at -47.539,-55.272 h1.52
  text "43.31mil (1.100mm)" at -32.303,-55.272 h1.52
  text "NPTH" at -3.102,-55.272 h1.52
  text "Round" at 9.747,-55.272 h1.52
  text "Pad" at 28.386,-55.272 h1.52
  text "2" at -47.539,-59.082 h1.52
  text "61.81mil (1.570mm)" at -32.303,-59.082 h1.52
  text "PTH" at -3.102,-59.082 h1.52
  text "Round" at 9.747,-59.082 h1.52
  text "Pad" at 28.386,-59.082 h1.52
  text "2" at -47.539,-62.892 h1.52
  text "133.86mil (3.400mm)" at -32.303,-62.892 h1.52
  text "PTH" at -3.102,-62.892 h1.52
  text "Round" at 9.747,-62.892 h1.52
  text "Pad" at 28.386,-62.892 h1.52
  text "4" at -47.539,-66.702 h1.52
  text "50.00mil (1.270mm)" at -32.303,-66.702 h1.52
  text "PTH" at -3.102,-66.702 h1.52
  text "Round" at 9.747,-66.702 h1.52
  text "Pad" at 28.386,-66.702 h1.52
  text "Layer" at 143.71,-66.866 h1.52
  text "Name" at 154.122,-66.866 h1.52
  text "Material" at 180.53,-66.866 h1.52
  text "Thickness" at 219.381,-66.866 h1.52
  text "Constant" at 235.887,-66.866 h1.52
  text "Board Layer Stack" at 250.361,-66.866 h1.52
  text "1" at 143.71,-69.914 h1.52
  text "Top Overlay" at 154.122,-69.914 h1.52
  text "12" at -47.539,-70.512 h1.52
  text "35.04mil (0.890mm)" at -32.303,-70.512 h1.52
  text "PTH" at -3.102,-70.512 h1.52
  text "Round" at 9.747,-70.512 h1.52
  text "Pad" at 28.386,-70.512 h1.52
  text "2" at 143.71,-72.962 h1.52
  text "Top Solder" at 154.122,-72.962 h1.52
  text "Solder Resist" at 180.53,-72.962 h1.52
  text "0.40mil" at 219.381,-72.962 h1.52
  text "3.5" at 235.887,-72.962 h1.52
  text "272" at -47.539,-74.322 h1.52
  text "10.00mil (0.254mm)" at -32.303,-74.322 h1.52
  text "PTH" at -3.102,-74.322 h1.52
  text "Round" at 9.747,-74.322 h1.52
  text "(Mixed)" at 28.386,-74.322 h1.52
  text "3" at 143.71,-76.01 h1.52
  text "Top Layer 1" at 154.122,-76.01 h1.52
  text "Copper" at 180.53,-76.01 h1.52
  text "2.10mil" at 219.381,-76.01 h1.52
  text "297 Total" at -47.539,-78.132 h1.52
  text "4" at 143.71,-79.058 h1.52
  text "Dielectric1" at 154.122,-79.058 h1.52
  text "370HR(1ply 1080&1ply 106)" at 180.53,-79.058 h1.52
  text "4.30mil" at 219.381,-79.058 h1.52
  text "4.04" at 235.887,-79.058 h1.52
  text "Slot definitions :" at -60.389,-81.814 h1.52
  text "Routed Path Length" at -34.158,-81.814 h1.52
  text "= Calculated from tool start centre position to tool end centre position." at -6.15,-81.814 h1.52
  text "5" at 143.71,-82.106 h1.52
  text "Inner Layer 2" at 154.122,-82.106 h1.52
  text "Copper" at 180.53,-82.106 h1.52
  text "2.70mil" at 219.381,-82.106 h1.52
  text "Hole Length" at -34.158,-84.354 h1.52
  text "= Routed Path Length + Tool Size = Slot length as defined in the PCB layout" at -16.561,-84.354 h1.52
  text "6" at 143.71,-85.154 h1.52
  text "Dielectric 2" at 154.122,-85.154 h1.52
  text "370HR" at 180.53,-85.154 h1.52
  text "42.00mil" at 219.381,-85.154 h1.52
  text "4.04" at 235.887,-85.154 h1.52
  text "7" at 143.71,-88.202 h1.52
  text "Internal Plane 3" at 154.122,-88.202 h1.52
  text "Copper" at 180.53,-88.202 h1.52
  text "2.70mil" at 219.381,-88.202 h1.52
  text "8" at 143.71,-91.25 h1.52
  text "Dielectric 3" at 154.122,-91.25 h1.52
  text "370HR(1ply 1080&1ply 106)" at 180.53,-91.25 h1.52
  text "4.30mil" at 219.381,-91.25 h1.52
  text "4.04" at 235.887,-91.25 h1.52
  text "9" at 143.71,-94.298 h1.52
  text "Bottom Layer 4" at 154.122,-94.298 h1.52
  text "Copper" at 180.53,-94.298 h1.52
  text "2.10mil" at 219.381,-94.298 h1.52
  text "10" at 143.71,-97.346 h1.52
  text "Bottom Solder" at 154.122,-97.346 h1.52
  text "Solder Resist" at 180.53,-97.346 h1.52
  text "0.40mil" at 219.381,-97.346 h1.52
  text "3.5" at 235.887,-97.346 h1.52
  text "11" at 143.71,-100.394 h1.52
  text "Bottom Overlay" at 154.122,-100.394 h1.52
  text ".ProjectRevisionFAB" at 286.715,-120.294 h2.54
  text "DOCUMENT NUMBER:" at 257.675,-128.91 h0.51
  text ".ProjectBoardNumber" at 261.29,-131.826 h2.03
  text "04-" at 257.925,-131.91 h2.54
  text ".ProjectRevisionART" at 272.499,-136.503 h2.54
TITLE MIRROR (M17):
  lines w0.1: -78.075,-114.91 -42.255,-114.91 -42.255,-111.91 ; -76.975,-136.545 -76.975,-135.275 ; -76.975,-135.91 -66.815,-135.91 ; -76.975,-134.71 -76.975,-133.71 ; -76.975,-134.21 -66.975,-134.21 ; -74.435,-136.545 -74.435,-135.275 ; -71.975,-134.51 -71.975,-133.91 ; -71.895,-136.545 -71.895,-135.275 ; -69.355,-136.545 -69.355,-135.275 ; -66.975,-134.71 -66.975,-133.71 ; -66.815,-136.545 -66.815,-135.275
  lines w0.127: -83.175,-82.085 -78.095,-82.085 ; -83.175,-21.76 -78.095,-21.76 ; -83.175,38.565 -78.095,38.565 ; -78.095,-132.91 3.725,-132.91 ; -78.095,-126.91 3.725,-126.91 ; -78.075,-120.91 3.745,-120.91 ; -78.075,-111.91 37.745,-111.91 37.745,-137.33 ; -62.775,-137.33 -62.775,-126.91 ; -55.275,-137.33 -55.275,-132.91 ; -42.275,-132.91 -42.275,-126.91 ; -24.255,-137.33 -24.255,-120.91 ; -19.675,-142.41 -19.675,-137.33 ; -19.675,93.81 -19.675,98.89 ; 3.745,-137.33 3.745,-111.91 ; 43.825,-142.41 43.825,-137.33 ; 43.825,93.81 43.825,98.89 ; 107.325,-142.41 107.325,-137.33 ; 107.325,93.81 107.325,98.89 ; 170.825,-142.41 170.825,-137.33 ; 170.825,93.81 170.825,98.89 ; 234.325,-142.41 234.325,-137.33 ; 234.325,93.81 234.325,98.89 ; 292.721,-82.05 297.801,-82.05 ; 292.745,-21.76 297.825,-21.76 ; 292.747,38.6 297.827,38.6 ; -83.175,-142.41 -83.175,98.89 297.825,98.89 297.825,-142.41 -83.175,-142.41 ; -78.095,-137.33 -78.095,93.81 292.745,93.81 292.745,-137.33 -78.095,-137.33
  text "6" at -50.841,95.588 h0.51
  text "5" at 12.786,95.588 h0.51
  text "4" at 76.26,95.588 h0.51
  text "3" at 139.93,95.588 h0.51
  text "2" at 203.159,95.588 h0.51
  text "1" at 266.549,95.588 h0.51
  text "A" at -80,66.556 h0.51
  text "A" at 295.92,66.556 h0.51
  text "B" at -80,6.104 h0.51
  text "B" at 295.92,6.104 h0.51
  text "C" at -80,-54.221 h0.51
  text "C" at 296.024,-54.414 h0.51
  text "PROJECT PART NUMBER:" at -43.255,-113.91 h0.51
  text "TITLE:" at 2.745,-113.91 h0.51
  text ".ProjectpartNumber" at -63.255,-114.16 h0.51
  text "D" at -80,-114.419 h0.51
  text "D" at 295.92,-114.419 h0.51
  text ".ProjectTitle" at 2.745,-118.91 h0.51
  text "GERBER FILE:" at -25.255,-122.91 h0.51
  text "PCB DESIGNER:" at 2.745,-122.91 h0.51
  text ".Plot_File_Name" at -25.255,-125.91 h0.51
  text ".ProjectDrawnBy" at 2.745,-125.91 h0.51
  text "M" at 34.745,-127.91 h0.51
  text "DATE:" at -63.975,-128.91 h0.51
  text "BOARD NUMBER:" at -25.275,-128.91 h0.51
  text "ENGINEER:" at 2.725,-128.91 h0.51
  text "Microchip Technology Inc." at 35.975,-131.17 h0.51
  text ".PRINT_DATE" at -63.975,-131.91 h0.51
  text ".ProjectBoardNumber" at -30.275,-131.91 h0.51
  text "04-" at -25.275,-131.91 h0.51
  text ".ProjectEngineer" at 2.725,-131.91 h0.51
  text "2355 W. Chandler Blvd." at 34.745,-133.91 h0.51
  text "LAYER NAME:" at -25.275,-134.41 h0.51
  text "10mm" at -63.275,-134.51 h0.51
  text "REV:" at -56.025,-134.66 h0.51
  text "PCB FILE NAME:" at 2.725,-134.66 h0.51
  text "400mil" at -63.175,-136.21 h0.51
  text "Chandler, AZ  85224" at 33.745,-136.41 h0.51
  text ".PCB_FILE_NAME_NO_PATH" at 2.725,-136.66 h0.51
  text "6" at -50.841,-140.632 h0.51
  text "5" at 12.786,-140.632 h0.51
  text "4" at 76.26,-140.632 h0.51
  text "3" at 139.93,-140.632 h0.51
  text "2" at 203.159,-140.632 h0.51
  text "1" at 266.549,-140.632 h0.51

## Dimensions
1.143,0 to 10.668,6.224 on Drill Drawing
10.668,19.839 to 0,22.098 on Drill Drawing
0,22.098 to 54.737,22.098 on Drill Drawing
-2.54,0 to 0,22.098 on Drill Drawing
